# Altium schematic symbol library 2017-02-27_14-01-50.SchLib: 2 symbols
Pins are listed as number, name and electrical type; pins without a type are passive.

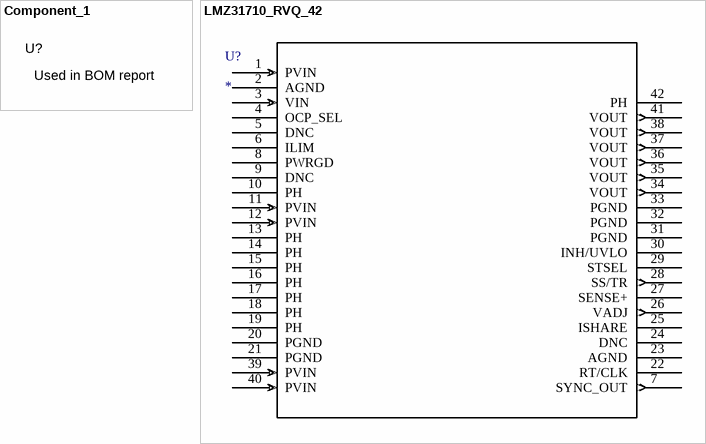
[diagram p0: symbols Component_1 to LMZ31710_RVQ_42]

## Component_1
designator U?, comment Used in BOM report
SymbolVersion: use current date i.e. 2008-05-20; SymbolCreator: Use a-id; CompType: Used in some BOM reports.  Useful for finding later.; U/M: EA, IN, or GM

## LMZ31710_RVQ_42
designator U?
Imported; Manufacturer_Part_Number: lmz31710_rvq_42; Vendor: Texas Instruments
footprint RVQ42
pins: 1 PVIN (in), 2 AGND (power), 3 VIN (in), 4 OCP_SEL, 5 DNC, 6 ILIM, 7 SYNC_OUT (out), 8 PWRGD (power), 9 DNC, 10 PH, 11 PVIN (in), 12 PVIN (in), 13 PH, 14 PH, 15 PH, 16 PH, 17 PH, 18 PH, 19 PH, 20 PGND (power), 21 PGND (power), 22 RT/CLK, 23 AGND (power), 24 DNC, 25 ISHARE, 26 VADJ (out), 27 SENSE+, 28 SS/TR (out), 29 STSEL, 30 INH/UVLO, 31 PGND (power), 32 PGND (power), 33 PGND (power), 34 VOUT (out), 35 VOUT (out), 36 VOUT (out), 37 VOUT (out), 38 VOUT (out), 39 PVIN (in), 40 PVIN (in), 41 VOUT (out), 42 PH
